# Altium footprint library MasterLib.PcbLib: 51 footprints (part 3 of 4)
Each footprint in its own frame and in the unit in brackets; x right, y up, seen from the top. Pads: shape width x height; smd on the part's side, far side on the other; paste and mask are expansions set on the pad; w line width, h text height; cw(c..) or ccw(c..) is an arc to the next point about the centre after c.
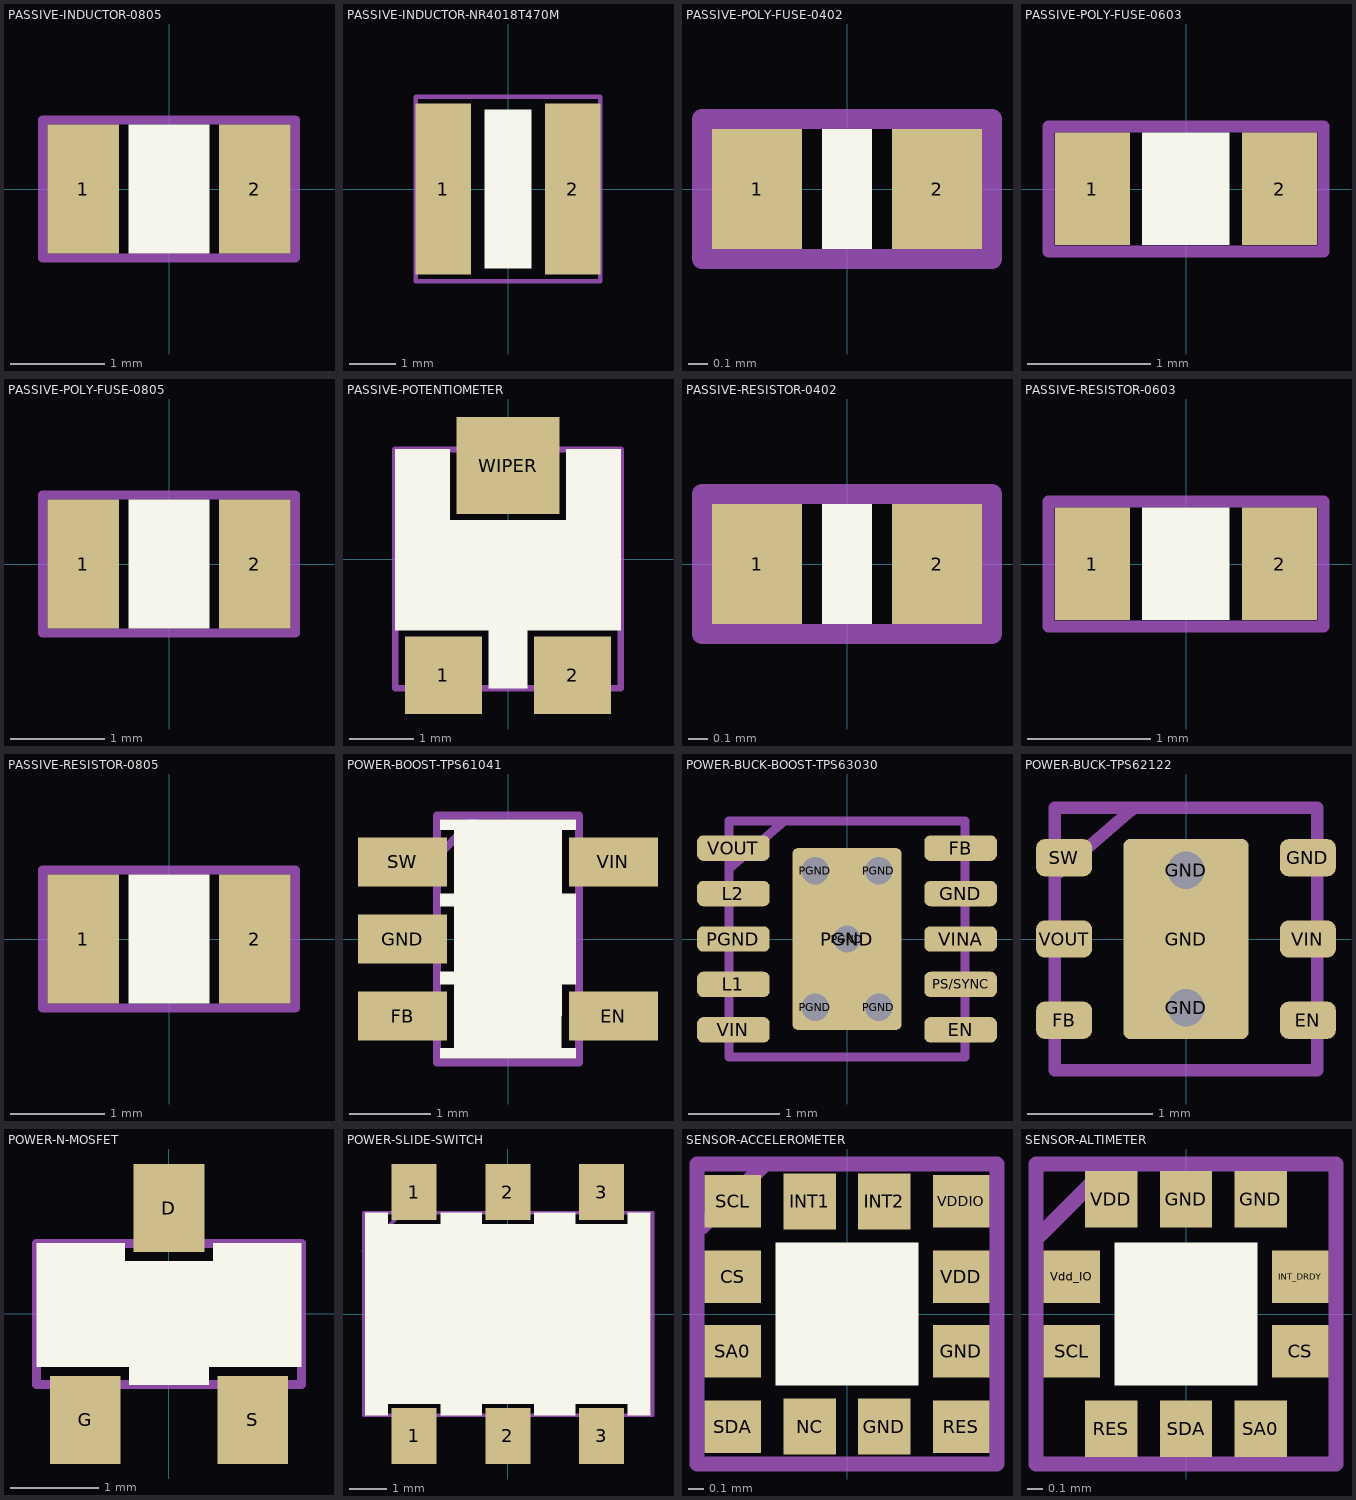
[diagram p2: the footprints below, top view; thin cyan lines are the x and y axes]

## PASSIVE-INDUCTOR-0805 [mil]
pads (2):
  rect 30x54 smd: 1(-36,0) 2(36,0)
Top Overlay:
  rectangle: -17,-27 17,27
Assembly Top:
  lines w3.94: -53,-29 -53,29 53,29 53,-29 -53,-29
  text ".Designator" at -23.62,-7.87 h15.75
3D body "PASSIVE-INDUCTOR-0805.step": height 44.62, standoff -2.62, extent -39.37,-24.6 39.37,24.6

## PASSIVE-INDUCTOR-NR4018T470M [mm]
pads (2):
  rect 1.2x3.7 smd: 1(-1.4,0) 2(1.4,0)
Top Overlay:
  rectangle: -0.508,-1.727 0.508,1.727
Assembly Top:
  lines w0.1: -2,-2 -2,2 2,2 2,-2 -2,-2
  text ".Designator" at -0.6,-0.2 h0.4
3D body "PASSIVE-INDUCTOR-NR4018T470M.step": height 1.73, standoff -0.07, extent -2.096,-2.098 2.096,2.098

## PASSIVE-POLY-FUSE-0402 [mil]
pads (2):
  rect 18x24 smd: 1(-18,0) 2(18,0)
Top Overlay:
  rectangle: -5,-12 5,12
Assembly Top:
  lines w3.94: -29,-14 29,-14 29,14 -29,14 -29,-14
  text ".Designator" at -23.62,-7.87 h15.75
3D body "PASSIVE-POLY-FUSE-0402.step": height 16.84, standoff -2.84, extent -19.68,-12.79 19.69,12.8

## PASSIVE-POLY-FUSE-0603 [mil]
pads (2):
  rect 24x36 smd: 1(-30,0) 2(30,0)
Top Overlay:
  rectangle: -14,-18 14,18
Assembly Top:
  lines w3.94: -44,-20 44,-20 44,20 -44,20 -44,-20
  text ".Designator" at -23.62,-7.87 h15.75
3D body "PASSIVE-POLY-FUSE-0603.step": height 26.76, standoff -2.76, extent -31.49,-15.74 31.5,15.75

## PASSIVE-POLY-FUSE-0805 [mil]
pads (2):
  rect 30x54 smd: 1(-36,0) 2(36,0)
Top Overlay:
  rectangle: -17,-27 17,27
Assembly Top:
  lines w3.94: -53,-29 -53,29 53,29 53,-29 -53,-29
  text ".Designator" at -23.62,-7.87 h15.75
3D body "PASSIVE-POLY-FUSE-0805.step": height 30.73, standoff -2.73, extent -39.37,-24.6 39.37,24.61

## PASSIVE-POTENTIOMETER [mm]
pads (3):
  rect 1.2x1.2 smd: 1(-1,-1.8) 2(1,-1.8)
  rect 1.6x1.5 smd: WIPER(0,1.45)
Top Overlay:
  region: -1.75,1.7 -0.9,1.7 -0.9,0.6 0.9,0.6 0.9,1.7 1.75,1.7 1.75,-1.1 0.3,-1.1 0.3,-2 -0.3,-2 -0.3,-1.1 -1.75,-1.1
Assembly Top:
  lines w0.1: -1.75,-2 -1.75,1.7 1.75,1.7 1.75,-2 -1.75,-2
  text ".Designator" at -0.6,-0.2 h0.4
3D body "PASSIVE-POTENTIOMETER.step": height 1.08, standoff -0.07, extent -1.8,-2.088 1.8,1.875

## PASSIVE-RESISTOR-0402 [mil]
pads (2):
  rect 18x24 smd: 1(-18,0) 2(18,0)
Top Overlay:
  rectangle: -5,-12 5,12
Assembly Top:
  lines w3.94: -29,-14 29,-14 29,14 -29,14 -29,-14
  text ".Designator" at -23.62,-7.87 h15.75
3D body "PASSIVE-RESISTOR-0402.step": height 12.17, standoff -4.17, extent -19.68,-9.84 19.69,9.85

## PASSIVE-RESISTOR-0603 [mil]
pads (2):
  rect 24x36 smd: 1(-30,0) 2(30,0)
Top Overlay:
  rectangle: -14,-18 14,18
Assembly Top:
  lines w3.94: -44,-20 -44,20 44,20 44,-20 -44,-20
  text ".Designator" at -23.62,-7.87 h15.75
3D body "PASSIVE-RESISTOR-0603.step": height 15.15, standoff -3.15, extent -31.49,-15.74 31.5,15.75

## PASSIVE-RESISTOR-0805 [mil]
pads (2):
  rect 30x54 smd: 1(-36,0) 2(36,0)
Top Overlay:
  rectangle: -17,-27 17,27
Assembly Top:
  lines w3.94: -53,-29 -53,29 53,29 53,-29 -53,-29
  text ".Designator" at -23.62,-7.87 h15.75
3D body "PASSIVE-RESISTOR-0805.step": height 17.14, standoff -3.14, extent -39.37,-24.6 39.37,24.61

## POWER-BOOST-TPS61041 [mm]
pads (5):
  rect 1.1x0.6 smd: EN(1.3,-0.95) FB(-1.3,-0.95) GND(-1.3,0) SW(-1.3,0.95) VIN(1.3,0.95)
Top Overlay:
  region: -0.838,1.473 0.838,1.473 0.838,1.346 0.66,1.346 0.661,0.559 0.838,0.559 0.838,0.457 0.838,-0.559 0.66,-0.559 0.66,-1.346 0.838,-1.346 0.838,-1.473 -0.838,-1.473 -0.838,-1.346 -0.66,-1.346 -0.66,-0.559 -0.838,-0.559 -0.838,-0.406 -0.66,-0.406 -0.66,0.406 -0.838,0.406 -0.838,0.559 -0.66,0.559 -0.66,1.346 -0.838,1.346
Assembly Top:
  lines w0.1: -0.875,1.01 -0.403,1.503 ; -0.875,-1.525 -0.875,1.525 0.875,1.525 0.875,-1.525 -0.875,-1.525
  text ".Designator" at 0.2,-0.6 h0.4
3D body "POWER-BOOST-TPS61041.step": height 1.37, standoff -0.08, extent -1.499,-1.525 1.499,1.523

## POWER-BUCK-BOOST-TPS63030 [mm]
pads (16):
  rrect50% 0.8x0.28 smd: EN(1.25,-1) FB(1.25,1) GND(1.25,0.5) L1(-1.25,-0.5) L2(-1.25,0.5) PGND(-1.25,0) PS/SYNC(1.25,-0.5) VIN(-1.25,-1) VINA(1.25,0) VOUT(-1.25,1)
  round 0.4 hole 0.3: PGND(-0.35,-0.75) PGND(0,0) PGND(0.35,-0.75) PGND(0.35,0.75)
  round 0.4 hole 0.3 paste+0: PGND(-0.35,0.75)
  rrect10% 1.2x2 smd: PGND(0,0)
Assembly Top:
  lines w0.1: -1.287,0.779 -0.686,1.3 ; -1.3,-1.3 -1.3,1.3 1.3,1.3 1.3,-1.3 -1.3,-1.3
  text ".Designator" at 0.2,-0.6 h0.4
3D body "POWER-BUCK-BOOST-TPS63030.step": height 0.72, standoff -0.08, extent -1.3,-1.3 1.3,1.3

## POWER-BUCK-TPS62122 [mm]
pads (9):
  rrect50% 0.45x0.3 smd: EN(0.975,-0.65) FB(-0.975,-0.65) GND(0.975,0.65) SW(-0.975,0.65) VIN(0.975,0) VOUT(-0.975,0)
  round 0.4 hole 0.3: GND(0,-0.55) GND(0,0.55)
  rrect10% 1x1.6 smd: GND(0,0)
Assembly Top:
  lines w0.1: -1.041,0.509 -0.44,1.03 ; -1.05,-1.05 -1.05,1.05 1.05,1.05 1.05,-1.05 -1.05,-1.05
  text ".Designator" at 0.2,-0.6 h0.4
3D body "POWER-BUCK-TPS62122.step": height 0.73, standoff -0.09, extent -1.058,-1.05 1.05,1.058

## POWER-N-MOSFET [mm]
height 0.35
pads (3):
  rect 0.8x1 smd: D(0,1.2) G(-0.95,-1.2) S(0.95,-1.2)
Top Overlay:
  region: -0.5,0.8 -0.5,0.6 0.5,0.6 0.5,0.8 1.5,0.8 1.5,-0.6 0.45,-0.6 0.45,-0.8 -0.45,-0.8 -0.45,-0.6 -1.5,-0.6 -1.5,0.8
Assembly Top:
  lines w0.1: -1.5,-0.8 -1.5,0.8 1.5,0.8 1.5,-0.8 -1.5,-0.8
3D body "POWER-N-MOSFET.step": height 1.32, standoff -0.08, extent -1.5,-1.399 1.5,1.4

## POWER-SLIDE-SWITCH [mm]
pads (6):
  rect 1.2x1.5 smd: 1(-2.5,-3.25) 1(-2.5,3.25) 2(0,-3.25) 2(0,3.25) 3(2.5,-3.25) 3(2.5,3.25)
Top Overlay:
  region: -3.8,2.7 -3.2,2.7 -3.2,2.4 -1.8,2.4 -1.8,2.7 -0.7,2.7 -0.7,2.4 0.7,2.4 0.7,2.7 1.8,2.7 1.8,2.4 3.2,2.4 3.2,2.7 3.8,2.7 3.8,-2.7 3.2,-2.7 3.2,-2.4 1.8,-2.4 1.8,-2.7 0.7,-2.7 0.7,-2.4 -0.7,-2.4 -0.7,-2.7 -1.8,-2.7 -1.8,-2.4 -3.2,-2.4 -3.2,-2.7 -3.8,-2.7
Assembly Top:
  lines w0.1: -3.85,1.675 -2.85,2.675 ; -3.85,-2.7 3.85,-2.7 3.85,2.7 -3.85,2.7 -3.85,-2.7
  text ".Designator" at -0.6,-0.2 h0.4
3D body "POWER-SLIDE-SWITCH.step": height 3.3, standoff 0, extent -3.875,-3.8 3.825,3.7

## SENSOR-ACCELEROMETER [mm]
height 1
pads (12):
  rect 0.375x0.35 smd: CS(-0.763,0.25) GND(0.763,-0.25) RES(0.763,-0.75) SA0(-0.763,-0.25) SCL(-0.763,0.75) SDA(-0.763,-0.75) VDD(0.763,0.25) VDDIO(0.763,0.75)
  rect 0.35x0.375 smd: GND(0.25,-0.75) INT1(-0.25,0.75) INT2(0.25,0.75) NC(-0.25,-0.75)
Top Overlay:
  region: -0.475,0.475 0.475,0.475 0.475,-0.475 -0.475,-0.475
Assembly Top:
  lines w0.1: -0.97,0.576 -0.556,0.99 ; -1,-1 1,-1 1,1 -1,1 -1,-1
  text ".Designator" at -0.6,-0.2 h0.4
3D body "SENSOR-ACCELEROMETER.step": height 0.5, standoff -0.08, extent -0.999,-1.003 1.001,0.997

## SENSOR-ALTIMETER [mm]
height 1
pads (10):
  rect 0.375x0.35 smd: CS(0.763,-0.25) INT_DRDY(0.763,0.25) SCL(-0.763,-0.25) Vdd_IO(-0.763,0.25)
  rect 0.35x0.375 smd: GND(0,0.765) GND(0.5,0.765) RES(-0.5,-0.765) SA0(0.5,-0.765) SDA(0,-0.765) VDD(-0.5,0.765)
Top Overlay:
  region: -0.475,0.475 0.475,0.475 0.475,-0.475 -0.475,-0.475
Assembly Top:
  lines w0.1: -1,0.5 -0.5,1 ; -1,-1 1,-1 1,1 -1,1 -1,-1
  text ".Designator" at -0.6,-0.2 h0.4
3D body "SENSOR-ALTIMETER.step": height 0.55, standoff -0.1, extent -1,-1 1,1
